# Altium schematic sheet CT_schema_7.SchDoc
size 274 x 160 mm
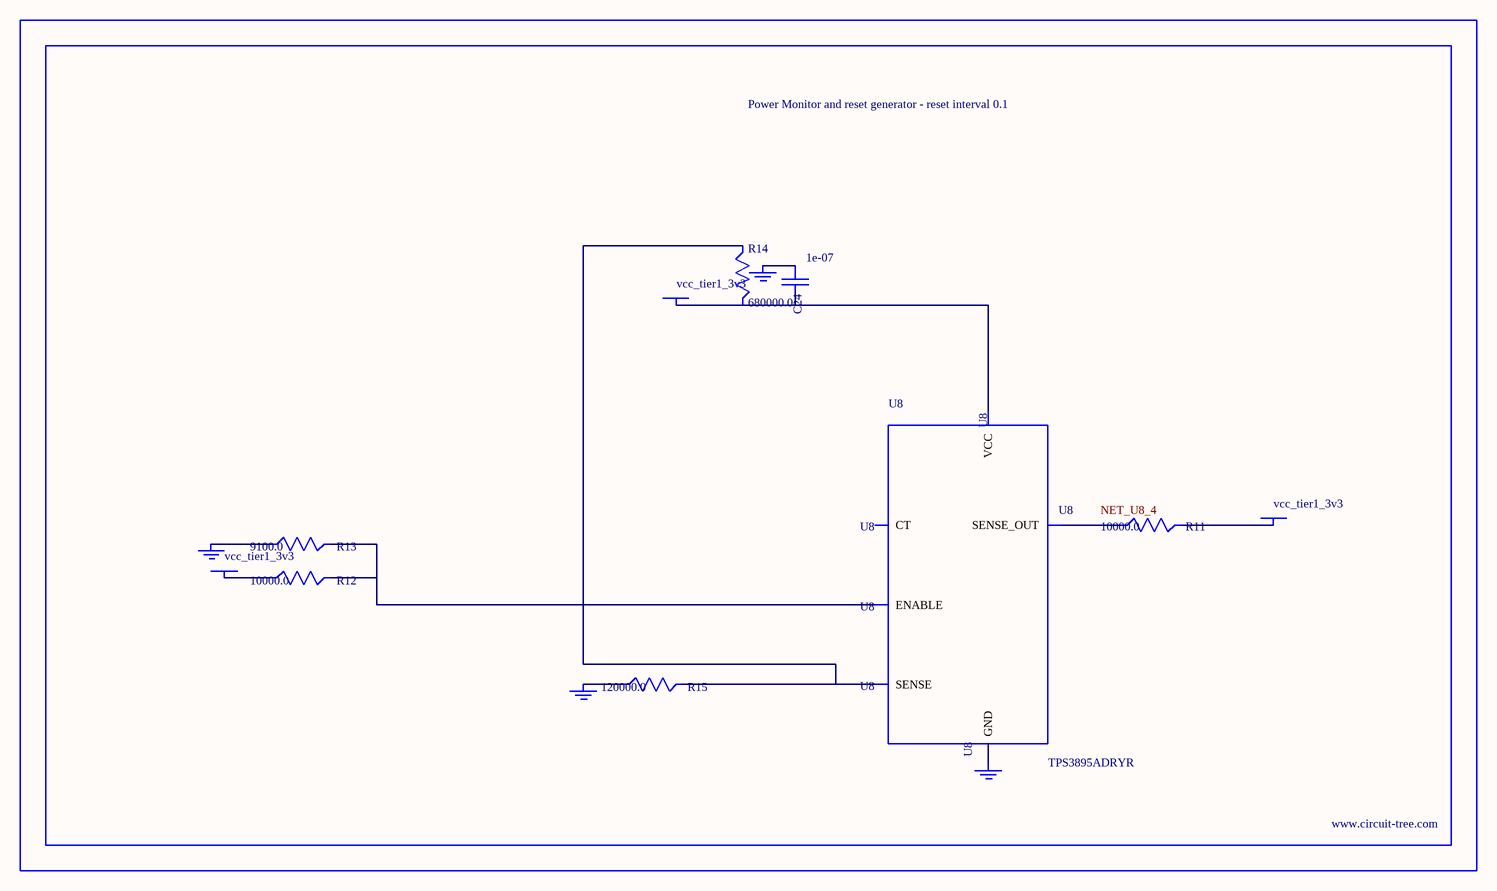
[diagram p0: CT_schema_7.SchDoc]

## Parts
BORDER6  (no value)
C24  1e-07  [C0402]
GND_INSTANCE_6_0  (no value)
GND_INSTANCE_6_1  (no value)
GND_INSTANCE_6_2  (no value)
GND_INSTANCE_6_3  (no value)
POWER_INSTANCE_6_0  vcc_tier1_3v3
POWER_INSTANCE_6_1  vcc_tier1_3v3
POWER_INSTANCE_6_2  vcc_tier1_3v3
R11  10000.0  [R0603]
R12  10000.0  [R0603]
R13  9100.0  [R0603]
R14  680000.0  [R0603]
R15  120000.0  [R0603]
U8  TPS3895ADRYR  [SON-6]

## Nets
NetC24_1: C24.1 GND_INSTANCE_6_2.0(GND)
NetC24_2: C24.2 POWER_INSTANCE_6_2.0(PWR) R14.2 U8.6(VCC)
NetGND_INSTANCE_6_0_0: GND_INSTANCE_6_0.0(GND) R13.1
NetGND_INSTANCE_6_1_0: GND_INSTANCE_6_1.0(GND) R15.1
NetGND_INSTANCE_6_3_0: GND_INSTANCE_6_3.0(GND) U8.2(GND)
NetPOWER_INSTANCE_6_0_0: POWER_INSTANCE_6_0.0(PWR) R12.1
NetPOWER_INSTANCE_6_1_0: POWER_INSTANCE_6_1.0(PWR) R11.2
NetR11_1: R11.1 U8.4(SENSE_OUT)
NetR12_2: R12.2 R13.2 U8.1(ENABLE)
NetR14_1: R14.1 R15.2 U8.3(SENSE)

Not connected (* = marked no-connect by the designer): U8 5(CT)

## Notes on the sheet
- Labels drawn without touching a wire or pin: NET_U8_4

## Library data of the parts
BORDER6 = BORDER_PAGE6
C24 = C0402C104K3RACTU
GND_INSTANCE_6_0-GND_INSTANCE_6_3 = GND
POWER_INSTANCE_6_0-POWER_INSTANCE_6_2 = PWR
R11 R12 = RC0603JR-0710KL
R13 = RC0603JR-079K1L
R14 = RC0603JR-07680KL
R15 = RC0603JR-07120KL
